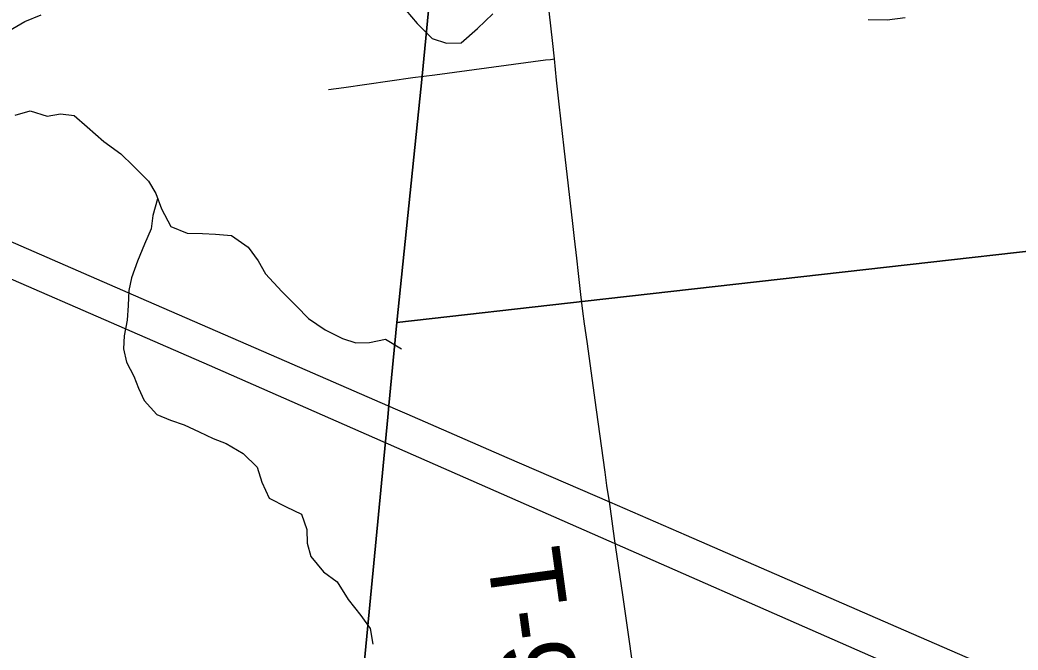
# Model space of a CAD drawing. Extents: x 0 to 34, y -5.4 to 22.
# Drawn here: x 3.075 to 3.849, y 18.333 to 18.822 of the extents above; entities that cross this region are included whole.
import ezdxf

# ---------------------------------------------------------------- set-up
doc = ezdxf.new("R2010")
doc.units = 0
for name, color, linetype in [('GM_X_Minor_River', 7, 'Continuous'), ('GM_X_Rail_Line', 7, 'Continuous'), ('GM_X_Township_Road', 7, 'Continuous'), ('GM_X_Township_Road_Text', 7, 'Continuous'), ('GM_X_US_Route', 7, 'Continuous')]:
    doc.layers.add(name, color=color, linetype=linetype)

msp = doc.modelspace()

# ---------------------------------------------------------------- linework, layer by layer
at = {"layer": 'GM_X_Minor_River'}
for points in [[(3.37381, 18.82941), (3.38271, 18.81902), (3.39425, 18.80744), (3.40555, 18.80384), (3.4169, 18.80402), (3.42958, 18.81518), (3.4415, 18.82674)], [(3.06586, 18.81344), (3.07847, 18.82081), (3.09105, 18.8259)], [(3.73245, 18.82214), (3.74721, 18.82189), (3.76125, 18.82393)], [(3.07082, 18.74811), (3.08261, 18.75133), (3.09579, 18.74731), (3.10603, 18.74903), (3.11661, 18.74771), (3.12668, 18.73882), (3.13974, 18.72759), (3.15282, 18.71788), (3.1625, 18.70862), (3.17442, 18.69665), (3.17993, 18.68708), (3.18428, 18.67525), (3.19162, 18.66147), (3.2044, 18.65632), (3.21612, 18.65612), (3.22633, 18.65556), (3.23881, 18.65459), (3.25152, 18.64565), (3.25929, 18.6349), (3.26518, 18.62493), (3.27781, 18.61106), (3.28898, 18.59987), (3.29828, 18.59023), (3.31138, 18.58128), (3.32489, 18.5746), (3.33506, 18.57139), (3.34566, 18.57159), (3.35819, 18.57403), (3.37055, 18.56662)], [(3.18138, 18.68315), (3.17776, 18.67005), (3.17645, 18.65983), (3.17133, 18.64778), (3.16581, 18.6346), (3.16106, 18.62178), (3.159, 18.61195), (3.15842, 18.60021), (3.15785, 18.58884), (3.15538, 18.57674), (3.15483, 18.56651), (3.15731, 18.55623), (3.16281, 18.54551), (3.16643, 18.53597), (3.17082, 18.52641), (3.18085, 18.51562), (3.19138, 18.51126), (3.20192, 18.50767), (3.21356, 18.50216), (3.22445, 18.49704), (3.2346, 18.49308), (3.24771, 18.48526), (3.25851, 18.47484), (3.2621, 18.46302), (3.26795, 18.45078), (3.28109, 18.44411), (3.2931, 18.43821), (3.29707, 18.42638), (3.29727, 18.41576), (3.30012, 18.40547), (3.31014, 18.39354), (3.32061, 18.38577), (3.32909, 18.37197), (3.3391, 18.35966), (3.34612, 18.34968), (3.34819, 18.3375)]]:
    msp.add_lwpolyline(points, dxfattribs=at)
at = {"layer": 'GM_X_Rail_Line'}
for points in [[(8.9, 19.21274), (8.9, 20.89996), (3.51334, 20.89996), (3.51219, 20.87627), (3.4778, 20.16974), (3.45998, 19.81882), (3.43026, 19.2337), (3.43013, 19.23114), (3.42966, 19.22639), (3.38649, 18.77815), (3.36693, 18.58719), (3.51308, 18.60367), (4.75049, 18.74323), (5.02549, 18.77424), (5.09598, 18.78056), (5.37805, 18.81401), (5.73126, 18.85946), (5.7334, 18.8597), (6.00448, 18.89084), (6.44961, 18.9373), (6.6792, 18.96033), (6.90536, 18.98227), (7.23153, 19.0156), (8.52011, 19.16909)], [(2.1, 20.20326), (2.1, 14.09996), (2.95271, 14.09996), (2.96406, 14.23243), (3.00585, 14.74625), (3.03821, 15.14547), (3.09667, 15.75174), (3.13002, 16.13264), (3.24317, 17.2942), (3.35989, 18.51362), (3.36075, 18.52261), (3.36693, 18.58719), (3.38649, 18.77815), (3.42966, 19.22639), (3.43013, 19.23114), (3.43026, 19.2337), (3.45998, 19.81882), (3.4778, 20.16974), (3.24172, 20.17559), (2.15373, 20.20256)]]:
    msp.add_lwpolyline(points, close=True, dxfattribs=at)
for points in [[(8.9, 15.59443), (8.9, 19.21274), (8.52011, 19.16909), (7.23153, 19.0156), (6.90536, 18.98227), (6.6792, 18.96033), (6.44961, 18.9373), (6.00448, 18.89084), (5.7334, 18.8597), (5.73126, 18.85946), (5.37805, 18.81401), (5.09598, 18.78056), (5.02549, 18.77424), (4.75049, 18.74323), (3.51308, 18.60367), (3.36693, 18.58719), (3.36075, 18.52261), (3.35989, 18.51362), (3.24317, 17.2942), (3.13002, 16.13264)], [(2.1, 19.04602), (2.50857, 18.86386), (2.51911, 18.86001), (3.22129, 18.55392), (4.01436, 18.20522), (4.73565, 17.89263), (4.95447, 17.79444), (5.89166, 17.38567), (5.94404, 17.36054), (5.98933, 17.3246), (6.01734, 17.2941), (6.04046, 17.25932), (6.05506, 17.23051), (6.12978, 17.03069)]]:
    msp.add_lwpolyline(points, dxfattribs=at)
at = {"layer": 'GM_X_Township_Road'}
for points in [[(3.5097, 18.60874), (3.50786, 18.62513), (3.50652, 18.6371), (3.50475, 18.65236), (3.50339, 18.66391), (3.49669, 18.72244), (3.49542, 18.7337), (3.49288, 18.75654), (3.49087, 18.77506), (3.4891, 18.79168), (3.48757, 18.80594), (3.48141, 18.86089), (3.47696, 18.90414), (3.47305, 18.9437), (3.47157, 18.95721), (3.47091, 18.9633), (3.46486, 19.01654), (3.45786, 19.08139), (3.4514, 19.14093), (3.45052, 19.14894), (3.45009, 19.15292), (3.447, 19.18143), (3.44039, 19.23462)], [(3.39634, 18.77939), (3.48228, 18.79086), (3.48599, 18.79131), (3.4891, 18.79168)], [(3.31402, 18.76795), (3.3259, 18.7694), (3.37937, 18.77713), (3.39634, 18.77939)], [(3.53198, 18.44776), (3.52989, 18.4605), (3.52848, 18.47096), (3.52178, 18.51934), (3.51446, 18.5722), (3.51252, 18.58591), (3.51125, 18.59586), (3.5097, 18.60874)], [(3.65224, 17.31758), (3.64913, 17.34553), (3.6491, 17.34717), (3.64893, 17.35353), (3.64834, 17.3722), (3.64537, 17.48712), (3.64376, 17.55857), (3.64145, 17.63995), (3.64092, 17.65284), (3.63982, 17.67289), (3.63894, 17.6831), (3.6374, 17.69579), (3.62033, 17.81578), (3.60862, 17.89634), (3.59967, 17.96097), (3.5862, 18.06198), (3.57758, 18.12228), (3.56937, 18.17947), (3.55931, 18.25335), (3.55403, 18.29213), (3.54211, 18.3758), (3.53562, 18.41945), (3.53265, 18.44251), (3.53198, 18.44776)]]:
    msp.add_lwpolyline(points, dxfattribs=at)
at = {"layer": 'GM_X_US_Route'}
for points in [[(2.67504, 18.81218), (2.69882, 18.80519), (2.72247, 18.7974), (2.74382, 18.78975), (2.76683, 18.78056), (2.80876, 18.76255), (2.90401, 18.72107), (2.9921, 18.68276), (3.1684, 18.60604), (3.28538, 18.5551), (3.36554, 18.52013), (3.37463, 18.51617)], [(3.37463, 18.51617), (3.45235, 18.48234), (3.53198, 18.44776)], [(3.53198, 18.44776), (3.5914, 18.42197), (3.74987, 18.35284), (3.82525, 18.31999), (3.94101, 18.26972), (4.17349, 18.16841), (4.37343, 18.08135), (4.52187, 18.01638), (4.71672, 17.93127), (4.85325, 17.87185), (4.97387, 17.81936), (5.01569, 17.80012), (5.05614, 17.7807), (5.085, 17.7662), (5.11338, 17.75129), (5.14605, 17.73386), (5.17239, 17.7191), (5.22351, 17.68935), (5.25618, 17.66937), (5.2871, 17.64974), (5.31777, 17.6291), (5.35054, 17.60643), (5.39057, 17.57826), (5.42978, 17.5482)]]:
    msp.add_lwpolyline(points, dxfattribs=at)

# ---------------------------------------------------------------- texts
at = {"layer": 'GM_X_Township_Road_Text'}
msp.add_text('T-95', height=0.056818, rotation=277.77808, dxfattribs=at).set_placement((3.43653, 18.40775))

doc.saveas('drawing.dxf')
